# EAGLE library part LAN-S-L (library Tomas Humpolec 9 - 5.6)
Integrated 10/100 Base-T RJ45 Through Hole MIC24 Series MIC24011-0101 ( Yellow--Green / 0°C to +70°C ) Features ? Optional PoE compatible designs ? Optional pin-outs and LEDs ? Industry standard connector footprint ? Optimum performance ? Cost effective ? RoHS compliant Typical Electrical Characteristics ? Inductance ... 350uH Min. 0.1Vrms, 100kHz, 8mADC ? Dielectic Rating ... 1500VAC for 1 m inute ? Turns Ratio ... 1CT:1CT ±2% ? Insertion Loss ... -1.0dB max. 1MHz-100MHz ? Return Loss ... -18dB min. 1MHz-30MHz ? Return Loss ... -16dB min. 30MHz-45MHz ? Return Loss ... -14dB min. 45MHz-60MHz ? Return Loss ... -12dB min. 60MHz-80MHz ? Cross Talk ... -35dB min. 1MHz-100MHz ? Common Mode Rejection ... -35dB min. 1MHz-100MHz Wurth Electronics Midcom, Inc. 121 Airport Drive?PO Box 1330 Watertown, SD 57201 T: 605.886.4385 ~ 605.886.4486 www.we-online.com ~ email: sales@midcom-inc.com http://www.tme.eu/cz/katalog/index.phtml?f_zamowienie=1#id_category%3D100189%26cleanParameters%3D
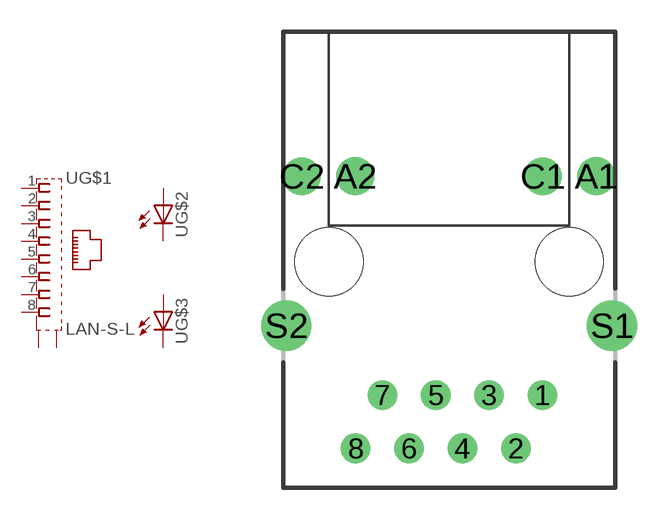
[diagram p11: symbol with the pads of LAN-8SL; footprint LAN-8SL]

Designator prefix -; gates G$1=LAN-8S G$2=LED G$3=LED

## LAN-S-L  [LAN-8SL]
1  G$1:1  pas
2  G$1:2  pas
3  G$1:3  pas
4  G$1:4  pas
5  G$1:5  pas
6  G$1:6  pas
7  G$1:7  pas
8  G$1:8  pas
A1  G$2:A  pas
A2  G$3:A  pas
C1  G$2:C  pas
C2  G$3:C  pas
S1  G$1:S1  pas
S2  G$1:S2  pas

## Footprint LAN-8SL (pad centres in mm)
drill 0.9 round: 1 4.445,-7.176; 2 3.175,-9.716; 3 1.905,-7.176; 4 0.635,-9.716; 5 -0.635,-7.176; 6 -1.905,-9.716; 7 -3.175,-7.176; 8 -4.445,-9.716
drill 1.2 round: A1 6.994,3.24; A2 -4.47,3.24; C1 4.454,3.235; C2 -7.01,3.235
drill 1.6 round: S1 7.745,-3.876; S2 -7.745,-3.876
hole 3.25 at 5.715,-0.826
hole 3.25 at -5.715,-0.826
